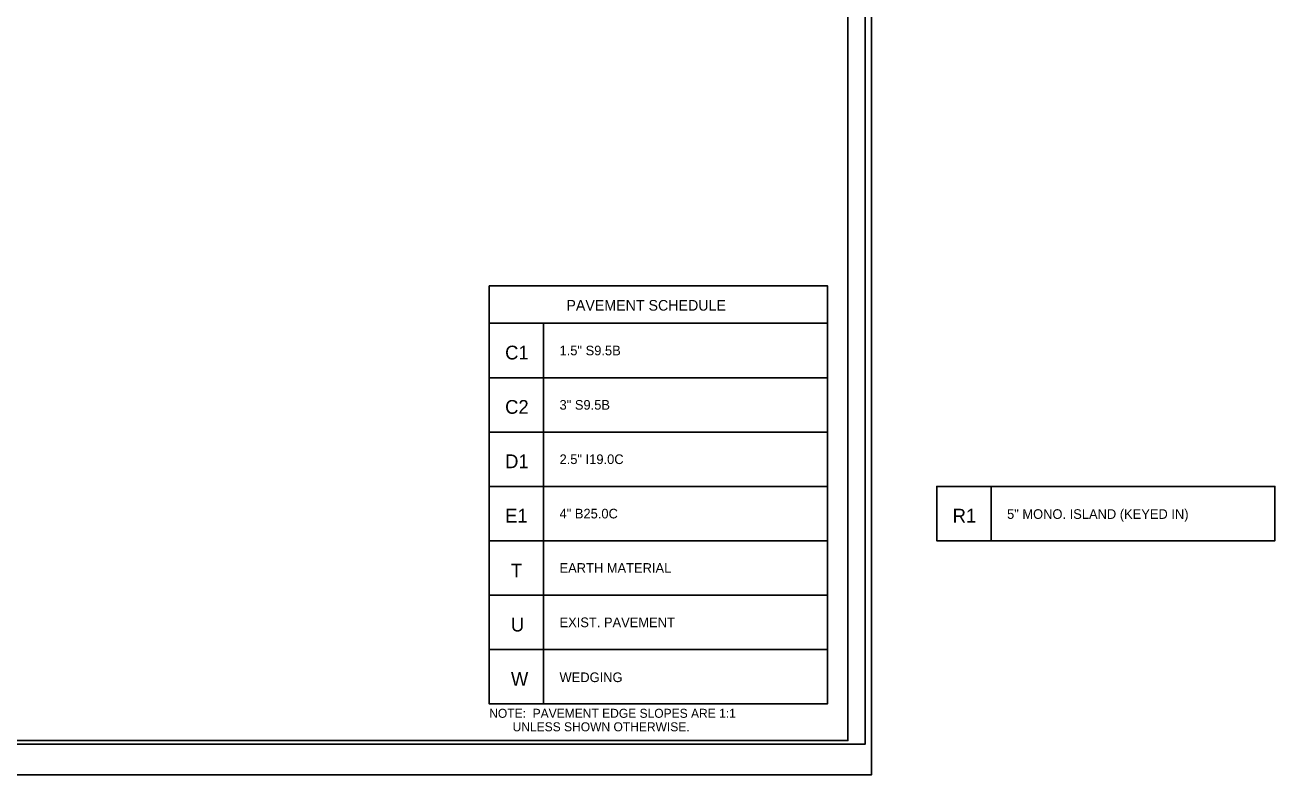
# Model space of a CAD drawing. Extents: x 1901718 to 1902220, y 193828 to 194187.
# Drawn here: x 1902072.8 to 1902163.6, y 193828 to 193882.5 of the extents above; entities that cross this region are included whole.
import ezdxf

# ---------------------------------------------------------------- set-up
doc = ezdxf.new("R2010")
doc.units = 0
for name, color, linetype in [('Old_Level_21', 7, 'Continuous'), ('Prop Pavement Schedule Description CELL', 7, 'Continuous'), ('Sheet Border Standard 30in CELL', 7, 'Continuous'), ('Sheet Cutting Line CELL', 7, 'Continuous'), ('Sheet Plot Border Inside CELL', 7, 'Continuous'), ('Sheet Plot Border Outside CELL', 7, 'Continuous')]:
    doc.layers.add(name, color=color, linetype=linetype)

msp = doc.modelspace()

# ---------------------------------------------------------------- linework, layer by layer
at = {"layer": 'Prop Pavement Schedule Description CELL'}
msp.add_lwpolyline([(1902106.492, 193863.527), (1902131.055, 193863.527), (1902131.055, 193860.801), (1902106.492, 193860.801)], close=True, dxfattribs=at)
for points in [[(1902110.439, 193856.854), (1902106.492, 193856.854), (1902106.492, 193860.801), (1902131.055, 193860.801), (1902131.055, 193856.854), (1902110.439, 193856.854), (1902110.439, 193860.801)], [(1902110.439, 193852.908), (1902106.492, 193852.908), (1902106.492, 193856.854), (1902131.055, 193856.854), (1902131.055, 193852.908), (1902110.439, 193852.908), (1902110.439, 193856.854)], [(1902110.439, 193848.961), (1902106.492, 193848.961), (1902106.492, 193852.908), (1902131.055, 193852.908), (1902131.055, 193848.961), (1902110.439, 193848.961), (1902110.439, 193852.908)], [(1902110.439, 193845.014), (1902106.492, 193845.014), (1902106.492, 193848.961), (1902131.055, 193848.961), (1902131.055, 193845.014), (1902110.439, 193845.014), (1902110.439, 193848.961)], [(1902142.936, 193845.014), (1902138.989, 193845.014), (1902138.989, 193848.961), (1902163.551, 193848.961), (1902163.551, 193845.014), (1902142.936, 193845.014), (1902142.936, 193848.961)], [(1902110.439, 193841.068), (1902106.492, 193841.068), (1902106.492, 193845.014), (1902131.055, 193845.014), (1902131.055, 193841.068), (1902110.439, 193841.068), (1902110.439, 193845.014)], [(1902110.439, 193837.121), (1902106.492, 193837.121), (1902106.492, 193841.068), (1902131.055, 193841.068), (1902131.055, 193837.121), (1902110.439, 193837.121), (1902110.439, 193841.068)], [(1902110.439, 193833.174), (1902106.492, 193833.174), (1902106.492, 193837.121), (1902131.055, 193837.121), (1902131.055, 193833.174), (1902110.439, 193833.174), (1902110.439, 193837.121)]]:
    msp.add_lwpolyline(points, dxfattribs=at)
at = {"layer": 'Sheet Border Standard 30in CELL'}
msp.add_lwpolyline([(1902132.544, 193935.514), (1901982.544, 193935.514), (1901982.544, 193830.514), (1902132.544, 193830.514)], close=True, dxfattribs=at)
at = {"layer": 'Sheet Cutting Line CELL'}
msp.add_line((1901965.844, 193828.014), (1902134.244, 193828.014), dxfattribs=at)
at = {"layer": 'Sheet Plot Border Inside CELL'}
msp.add_lwpolyline([(1902133.794, 193935.769), (1901967.144, 193935.769), (1901967.144, 193830.259), (1902133.794, 193830.259)], close=True, dxfattribs=at)
at = {"layer": 'Sheet Plot Border Outside CELL'}
msp.add_lwpolyline([(1902134.244, 193938.014), (1901965.844, 193938.014), (1901965.844, 193828.014), (1902134.244, 193828.014)], close=True, dxfattribs=at)

# ---------------------------------------------------------------- texts
at = {"layer": 'Old_Level_21'}
for s, height, p in [('W', 1, (1902108.068, 193834.493)), ('WEDGING', 0.7, (1902111.599, 193834.757)), ('NOTE:  PAVEMENT EDGE SLOPES ARE 1:1 ', 0.653, (1902106.492, 193832.165)), ('       UNLESS SHOWN OTHERWISE.', 0.653, (1902106.492, 193831.185))]:
    msp.add_text(s, height=height, dxfattribs=at).set_placement(p)
at = {"layer": 'Prop Pavement Schedule Description CELL'}
for s, height, p in [('PAVEMENT SCHEDULE', 0.77179, (1902112.098, 193861.721)), ('C1', 1, (1902107.648, 193858.177)), ('1.5" S9.5B', 0.7, (1902111.599, 193858.477)), ('C2', 1, (1902107.648, 193854.231)), ('3" S9.5B', 0.7, (1902111.599, 193854.531)), ('D1', 1, (1902107.648, 193850.284)), ('2.5" I19.0C', 0.7, (1902111.599, 193850.584)), ('E1', 1, (1902107.648, 193846.337)), ('4" B25.0C', 0.7, (1902111.599, 193846.637)), ('R1', 1, (1902140.144, 193846.337)), ('5" MONO. ISLAND (KEYED IN)', 0.7, (1902144.095, 193846.604)), ('T ', 1, (1902108.065, 193842.352)), ('EARTH MATERIAL', 0.7, (1902111.599, 193842.691)), ('U ', 1, (1902108.068, 193838.429)), ('EXIST. PAVEMENT', 0.7, (1902111.599, 193838.744))]:
    msp.add_text(s, height=height, dxfattribs=at).set_placement(p)

doc.saveas('drawing.dxf')
